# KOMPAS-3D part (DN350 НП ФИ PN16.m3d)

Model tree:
1. Операция без истории:1

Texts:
  DN350 НП ФИ PN16
  133 1 134 1 135 1 136 0 50 1|SPDS|133 1 134 1 135 1 136 0 50 1
  125 1 126 1 127 1 128 0 50 1|SPDS|125 1 126 1 127 1 128 0 50 1
  129 1 130 1 131 1 132 0 50 1|SPDS|129 1 130 1 131 1 132 0 50 1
